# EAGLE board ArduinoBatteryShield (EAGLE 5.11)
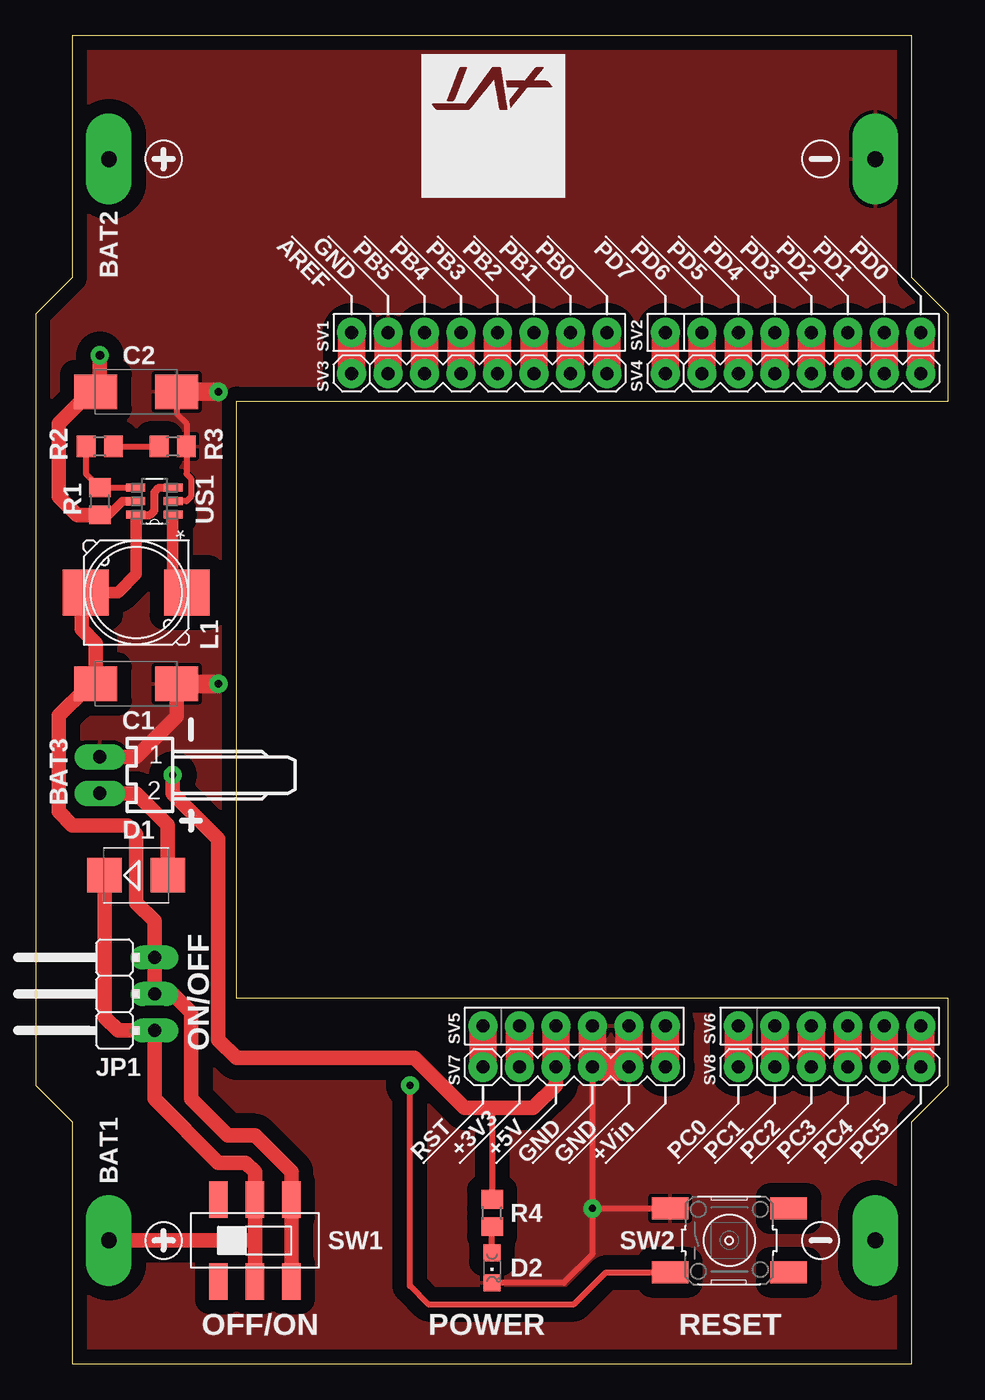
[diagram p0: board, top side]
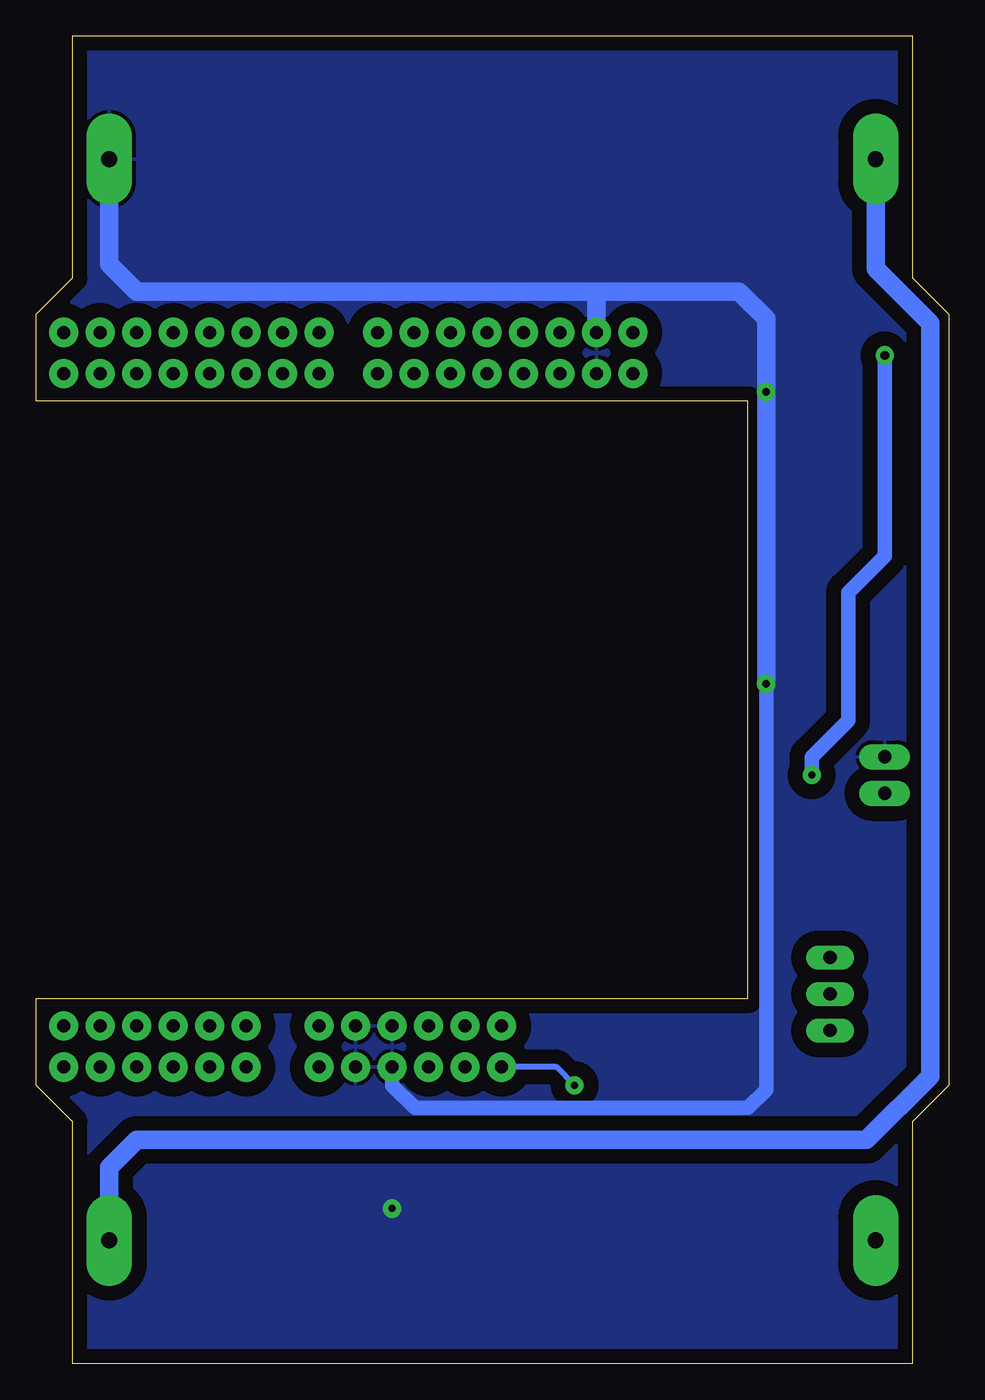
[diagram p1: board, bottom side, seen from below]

Size 63.5 x 92.39 mm. Coordinates in mm from the lower left corner, seen from the top.
Outline: 2.54,0 60.96,0 60.96,16.83 63.5,19.37 63.5,25.4 13.97,25.4 13.97,66.99 63.5,66.99 63.5,73.03 60.96,75.56 60.96,92.39 2.54,92.39 2.54,75.56 0,73.03 0,19.37 2.54,16.83 2.54,0
Copper layers (1*16): Top 0.035mm / dielectric 1.5mm / Bottom 0.035mm
Design rules "default": minimum track width 10mil, minimum drill 24mil, track to track 8mil, track to pad 8mil, pad to pad 8mil, via to via 8mil, smd to smd 8mil, copper to edge 40mil, drill to drill 8mil, minimum pad ring 10mil, minimum via ring 8mil, stop-mask expansion 4mil, vias tented up to drill 0mil, thermal gap 10mil

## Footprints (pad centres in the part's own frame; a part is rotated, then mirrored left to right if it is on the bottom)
AA_NO_FRAME = drill 1.1 pad 3.175 long: + 26.67,0; - -26.67,0
7395-02 = drill 0.914 pad 1.778 long: 1 1.27,0; 2 -1.27,0
SMC_C = smd 3 x 2.4: + -2.817,0; - 2.817,0
SMB = smd 2.4 x 2.4: A 2.2,0; C -2.2,0
CHIPLED_0805 = smd 1.2 x 1.2: A 0,-1.05; C 0,1.05
JP2W = drill 0.914 pad 1.676 long: 1 -2.54,-1.27; 2 0,-1.27; 3 2.54,-1.27
WE-PD_S/M = smd 3.175 x 3.175: 1 -3.518,0; 2 3.518,0
R0805 = smd 1.3 x 1.5: 1 -0.95,0; 2 0.95,0
FE08 = drill 0.914 pad 2.032 round: 1 -8.89,0; 2 -6.35,0; 3 -3.81,0; 4 -1.27,0; 5 1.27,0; 6 3.81,0; 7 6.35,0; 8 8.89,0
MA08-1 = drill 0.914 pad 2.032 round: 1 -8.89,0; 2 -6.35,0; 3 -3.81,0; 4 -1.27,0; 5 1.27,0; 6 3.81,0; 7 6.35,0; 8 8.89,0
FE06 = drill 0.914 pad 2.032 round: 1 -6.35,0; 2 -3.81,0; 3 -1.27,0; 4 1.27,0; 5 3.81,0; 6 6.35,0
MA06-1 = drill 0.914 pad 2.032 round: 1 -6.35,0; 2 -3.81,0; 3 -1.27,0; 4 1.27,0; 5 3.81,0; 6 6.35,0
HSS1280S = smd 1.27 x 2.54: 1 6.35,-0.318; 2 8.89,-0.318; 3 11.43,-0.318; 4 11.43,5.397; 5 8.89,5.397; 6 6.35,5.397
B3F-10XX_SMD = smd 2.54 x 1.524: 1 -4.128,2.223; 2 4.128,2.223; 3 -4.128,-2.223; 4 4.128,-2.223
SOT95P270X145-6N = smd 1.321 x 0.559: 1 -1.295,0.94; 2 -1.295,0; 3 -1.295,-0.94; 4 1.295,-0.94; 5 1.295,0; 6 1.295,0.94

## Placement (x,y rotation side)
BAT1  AA  [AA_NO_FRAME]  31.75,8.57 180 top
BAT2  AA  [AA_NO_FRAME]  31.75,83.82 180 top
BAT3  [7395-02]  4.45,40.96 90 top
C1  10uF  [SMC_C]  6.99,47.31 0 top
C2  10uF  [SMC_C]  6.99,67.63 0 top
D1  BYS10-45  [SMB]  6.99,33.97 0 top
D2  G  [CHIPLED_0805]  31.75,6.67 180 top
JP1  ON/OFF  [JP2W]  6.99,25.72 90 top
L1  10uH  [WE-PD_S/M]  6.99,53.66 0 top
R1  1M  [R0805]  4.45,60.01 270 top
R2  100k  [R0805]  4.45,63.82 180 top
R3  220k  [R0805]  9.53,63.82 180 top
R4  470  [R0805]  31.75,10.48 90 top
SV1  [FE08]  30.86,71.76 0 top
SV2  [FE08]  52.71,71.76 0 top
SV3  [MA08-1]  30.86,68.9 0 top
SV4  [MA08-1]  52.71,68.9 0 top
SV5  [FE06]  37.47,23.5 0 top
SV6  [FE06]  55.25,23.5 0 top
SV7  [MA06-1]  37.47,20.64 0 top
SV8  [MA06-1]  55.25,20.64 0 top
SW1  ON/OFF  [HSS1280S]  6.35,6.03 0 top
SW2  RESET  [B3F-10XX_SMD]  48.26,8.57 0 top
U$1  LOGOMEDIUM  [SIZE_M]  36.83,91.12 180 top
US1  MCP1640  [SOT95P270X145-6N]  8.26,60.01 180 top

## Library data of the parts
BAT1 BAT2 = AA_battery_holder
BAT3 = con-molex; OC_FARNELL: 9731601; OC_NEWARK: unknown
C1 C2 R1-R4 = rcl
D1 = diode
D2 = led
JP1 = jumper
L1 = wuerth-elektronik
SV1 SV2 SV5 SV6 = con-lsta; OC_FARNELL: unknown; OC_NEWARK: unknown
SV3 SV4 SV7 SV8 = con-lstb; OC_FARNELL: unknown; OC_NEWARK: unknown
SW1 = switch-misc
SW2 = switch-omron
U$1 = AVT_Logo
US1 = AA_battery_holder; MPN: MCP1640CT-I/CHY; OC_FARNELL: 1800208; OC_NEWARK: 73R3626; PACKAGE: SOT-6; SUPPLIER: Microchip

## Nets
+5V: C2.+ R1.2 R4.2 SV5.3 SV7.3 US1.5
+BAT: BAT1.+ D1.C JP1.1 SW1.2 SW1.5
+EXTBAT: BAT3.2 D1.A
GND: BAT2.- BAT3.1 C1.- C2.- D2.C R3.1 SV1.2 SV3.2 SV5.4 SV5.5 SV7.4 SV7.5 SW2.1 US1.2
N$1: L1.2 US1.1
N$2: BAT1.- BAT2.+
N$3: R2.1 R3.2
N$4: D2.A R4.1
N$5: R1.1 R2.2 US1.4
N$7: SV5.1 SV7.1 SW2.3
N$10: SV5.2 SV7.2
N$14: SV5.6 SV7.6
N$15: SV6.1 SV8.1
N$16: SV6.2 SV8.2
N$17: SV6.3 SV8.3
N$18: SV6.4 SV8.4
N$19: SV6.5 SV8.5
N$20: SV6.6 SV8.6
N$21: SV2.1 SV4.1
N$22: SV2.2 SV4.2
N$23: SV2.3 SV4.3
N$24: SV2.4 SV4.4
N$25: SV2.5 SV4.5
N$26: SV2.6 SV4.6
N$27: SV2.7 SV4.7
N$28: SV2.8 SV4.8
N$29: SV1.1 SV3.1
N$31: SV1.3 SV3.3
N$32: SV1.4 SV3.4
N$33: SV1.5 SV3.5
N$34: SV1.6 SV3.6
N$35: SV1.7 SV3.7
N$36: SV1.8 SV3.8
VIN: C1.+ JP1.2 JP1.3 L1.1 SW1.3 SW1.4 US1.3 US1.6

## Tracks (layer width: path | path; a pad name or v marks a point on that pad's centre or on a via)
+5V  (via drill 0.5 pad 1.27, 0.6 pad 1.27)
  Top 0.406: R4.2 31.75,17.78 32.39,17.78
  Top 0.559: R1.2 5.08,59.06
  Top 0.61: 5.08,59.06 6.03,60.01 US1.5
  Top 0.813: C2.+ 3.81,67.63 | R1.2
  Top 1.016: 3.81,67.63 1.59,65.4 1.59,60.32 2.86,59.06 R1.2 | v9.53,40.96 9.53,39.69 12.7,36.51 12.7,22.54 13.97,21.27 26.35,21.27 29.84,17.78 32.39,17.78 34.61,17.78 36.2,19.37 SV7.3 | v4.45,70.17 4.45,67.9 C2.+
  Top 1.93: SV7.3 SV5.3
  Bottom 1.016: v4.45,70.17 4.45,56.2 6.99,53.66 6.99,44.77 9.53,42.23 v9.53,40.96
+BAT
  Top 1.016: BAT1.+ 15.24,8.57 | D1.C 4.79,24.11 5.71,23.18 JP1.1 8.26,18.41 12.7,13.97 14.61,13.97 15.24,13.33 SW1.5 15.24,8.57 | 15.24,8.57 SW1.2
+EXTBAT
  Top 1.016: BAT3.2 6.99,39.69 9.19,37.49 D1.A
GND  (via drill 0.5 pad 1.27)
  Top 0.406: D2.C 36.73,5.62 38.73,7.62 v38.73,10.8 | US1.2 10.48,60.01 10.79,60.32 10.79,61.6 10.48,61.91 R3.1 | R3.1 10.47,65.41 9.8,66.08 C2.- | SV7.4 v38.73,10.8 | v38.73,10.8 SW2.1
  Top 0.559: R3.1
  Top 1.016: BAT3.1 6.99,42.23 9.8,45.04 C1.-
  Top 1.27: v12.7,67.63 C2.- | v12.7,47.31 C1.-
  Top 1.93: SV5.4 SV7.4 SV7.5 SV5.5 | SV1.2 SV3.2
  Bottom 1.016: 24.76,74.61 24.51,74.36 | SV7.4 38.73,19.37 37.15,17.78 13.97,17.78 12.7,19.05 v12.7,47.31
  Bottom 1.27: BAT2.- 58.42,76.52 56.52,74.61 24.76,74.61 14.61,74.61 12.7,72.71 v12.7,67.63 v12.7,47.31 | 24.51,74.36 SV1.2
  pour Bottom (isolate 1.016): 2.54,92.39 60.96,92.39 60.96,75.56 63.5,73.03 63.5,66.99 13.97,66.99 13.97,25.4 63.5,25.4 63.5,19.37 60.96,16.83 60.96,0 2.54,0 2.54,16.83 0,19.37 0,73.03 2.54,75.56
  pour Top (isolate 1.016): 2.54,92.39 60.96,92.39 60.96,75.56 63.5,73.03 63.5,66.99 13.97,66.99 13.97,25.4 63.5,25.4 63.5,19.37 60.96,16.83 60.96,0 2.54,0 2.54,16.83 0,19.37 0,73.03 2.54,75.56
N$1
  Top 0.406: 9.53,58.74 9.53,59.07 US1.1
  Top 0.813: L1.2 10.5,53.95 9.53,54.93 9.53,58.74
N$2
  Bottom 1.27: BAT2.+ 5.08,76.2 1.27,72.39 1.27,20 5.71,15.56 56.52,15.56 58.42,13.65 BAT1.-
N$3
  Top 0.406: R2.1 R3.2
N$4
  Top 0.406: D2.A R4.1
N$5
  Top 0.406: US1.4 R1.1 3.5,61.91 R2.2
N$7  (via drill 0.5 pad 1.27)
  Top 0.406: v26.04,19.37 26.04,5.4 27.3,4.13 37.47,4.13 39.69,6.35 SW2.3
  Top 1.93: SV7.1 SV5.1
  Bottom 0.406: SV7.1 27.3,20.64 v26.04,19.37
N$10
  Top 1.93: SV7.2 SV5.2
N$12  (via drill 0.5 pad 1.27)
  other vias: 26.04,19.37
N$14
  Top 1.93: SV7.6 SV5.6
N$15
  Top 1.93: SV8.1 SV6.1
N$16
  Top 1.93: SV8.2 SV6.2
N$17
  Top 1.93: SV8.3 SV6.3
N$18
  Top 1.93: SV8.4 SV6.4
N$19
  Top 1.93: SV8.5 SV6.5
N$20
  Top 1.93: SV8.6 SV6.6
N$21
  Top 1.93: SV4.1 SV2.1
N$22
  Top 1.93: SV4.2 SV2.2
N$23
  Top 1.93: SV4.3 SV2.3
N$24
  Top 1.93: SV4.4 SV2.4
N$25
  Top 1.93: SV4.5 SV2.5
N$26
  Top 1.93: SV4.6 SV2.6
N$27
  Top 1.93: SV4.7 SV2.7
N$28
  Top 1.93: SV4.8 SV2.8
N$29
  Top 1.93: SV3.1 SV1.1
N$31
  Top 1.93: SV3.3 SV1.3
N$32
  Top 1.93: SV3.4 SV1.4
N$33
  Top 1.93: SV3.5 SV1.5
N$34
  Top 1.93: SV3.6 SV1.6
N$35
  Top 1.93: SV3.7 SV1.7
N$36
  Top 1.93: SV3.8 SV1.8
VIN
  Top 0.559: US1.3 8.56,60.95 8.26,60.64 8.26,59.37 7.94,59.06 6.97,59.06 US1.6 6.99,59.04 6.99,58.74
  Top 0.813: L1.1 5.71,53.66 6.99,54.93 6.99,58.74
  Top 1.016: L1.1 3.17,53.66 3.17,51.12 4.17,50.12 C1.+ 3.85,46.99 3.49,46.99 1.59,45.08 1.59,38.42 2.54,37.47 6.35,37.47 6.99,36.83 6.99,32.07 8.26,30.8 JP1.3 JP1.2 9.53,25.72 10.79,24.45 10.79,18.41 13.34,15.88 15.24,15.88 17.78,13.33 SW1.4 SW1.3

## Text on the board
tNames: AREF | GND | PB5 | PB4 | PB3 | PB2 | PB1 | PB0 | PD7 | PD6 | PD5 | PD4 | PD3 | PD2 | PD1 | PD0 | ON/OFF | +3V3 | RST | +5V | GND | GND | +Vin | PC0 | PC1 | PC2 | PC3 | PC4 | PC5 | OFF/ON | POWER | RESET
